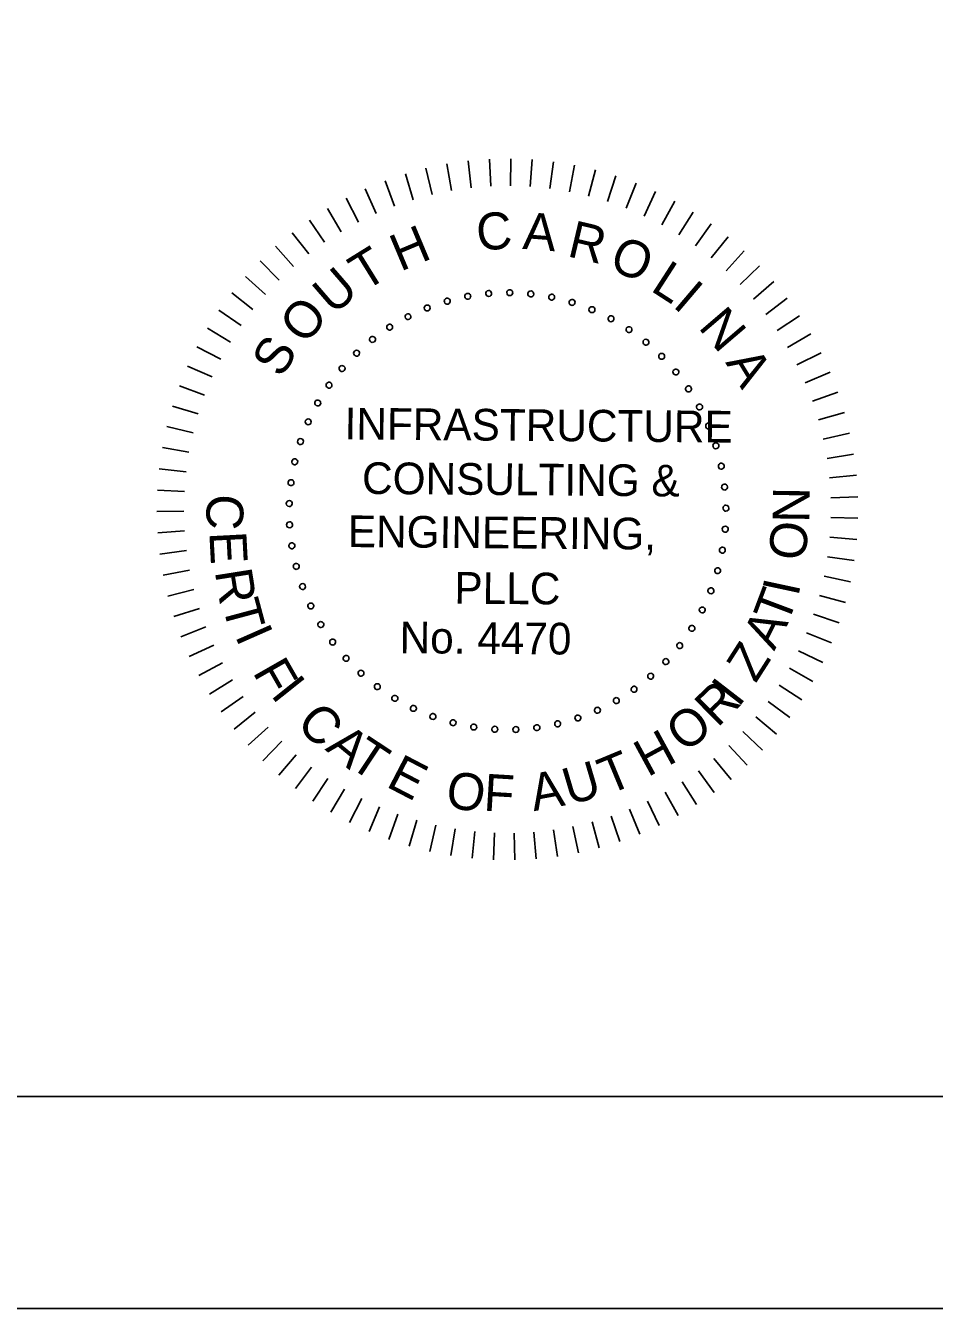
# Model space of a CAD drawing. Extents: x -125.5 to -89.4, y -5.1 to 16.9.
# Drawn here: x -100.338 to -98.192, y -5.066 to -2.039 of the extents above; entities that cross this region are included whole.
import ezdxf

# ---------------------------------------------------------------- set-up
doc = ezdxf.new("R2010")
doc.units = 0
for name, color, linetype in [('BR_BORDER LINES', 7, 'Continuous'), ('BR_TEXT', 7, 'Continuous'), ('Level 31', 7, 'Continuous')]:
    doc.layers.add(name, color=color, linetype=linetype)

msp = doc.modelspace()

# ---------------------------------------------------------------- linework, layer by layer
at = {"layer": 'BR_BORDER LINES'}
msp.add_line((-123.6994, -4.5662), (-90.0334, -4.5662), dxfattribs=at)
at = {"layer": 'BR_TEXT'}
for p, q in [((-99.2931, -2.3579), (-99.2858, -2.4212)), ((-99.2427, -2.3538), (-99.2394, -2.4174)), ((-99.1923, -2.3527), (-99.1928, -2.4164)), ((-99.1418, -2.3548), (-99.1462, -2.4183)), ((-99.0916, -2.3599), (-99.0999, -2.423)), ((-99.4412, -2.3886), (-99.4226, -2.4495)), ((-99.3925, -2.3754), (-99.3776, -2.4373)), ((-99.343, -2.3651), (-99.332, -2.4278)), ((-99.0418, -2.368), (-99.0539, -2.4305)), ((-98.9925, -2.3792), (-99.0084, -2.4408)), ((-99.489, -2.4048), (-99.4667, -2.4644)), ((-98.9441, -2.3933), (-98.9637, -2.4539)), ((-98.8966, -2.4104), (-98.9199, -2.4696)), ((-99.5813, -2.4457), (-99.5519, -2.5022)), ((-99.5358, -2.4238), (-99.5099, -2.482)), ((-98.8502, -2.4303), (-98.877, -2.488)), ((-99.6253, -2.4703), (-99.5926, -2.5249)), ((-98.8051, -2.453), (-98.8354, -2.509)), ((-98.7615, -2.4785), (-98.7952, -2.5325)), ((-99.6678, -2.4975), (-99.6318, -2.55)), ((-98.7195, -2.5065), (-98.7564, -2.5584)), ((-99.7086, -2.5273), (-99.6694, -2.5775)), ((-98.6793, -2.5371), (-98.7193, -2.5866)), ((-99.7475, -2.5595), (-99.7053, -2.6072)), ((-98.6411, -2.57), (-98.684, -2.617)), ((-99.7843, -2.5941), (-99.7393, -2.6391)), ((-99.819, -2.6308), (-99.7713, -2.673)), ((-98.6049, -2.6052), (-98.6506, -2.6495)), ((-98.571, -2.6426), (-98.6193, -2.684)), ((-99.8513, -2.6695), (-99.8012, -2.7087)), ((-98.5393, -2.6819), (-98.5901, -2.7204)), ((-99.8813, -2.7102), (-99.8288, -2.7463)), ((-98.5102, -2.7232), (-98.5632, -2.7584)), ((-99.9087, -2.7526), (-99.8541, -2.7854)), ((-98.4836, -2.7661), (-98.5387, -2.798)), ((-99.9334, -2.7965), (-99.877, -2.826)), ((-98.4597, -2.8105), (-98.5166, -2.839)), ((-99.9555, -2.842), (-99.8973, -2.8679)), ((-98.4385, -2.8563), (-98.497, -2.8813)), ((-99.9747, -2.8886), (-99.9151, -2.911)), ((-98.4202, -2.9034), (-98.4801, -2.9248)), ((-99.991, -2.9364), (-99.9302, -2.9551)), ((-98.4047, -2.9514), (-98.4659, -2.9691)), ((-100.0044, -2.9851), (-99.9426, -3)), ((-98.3922, -3.0004), (-98.4544, -3.0143)), ((-100.0149, -3.0345), (-99.9522, -3.0456)), ((-98.3828, -3.05), (-98.4456, -3.0601)), ((-100.0222, -3.0844), (-99.959, -3.0917)), ((-98.3763, -3.1), (-98.4397, -3.1063)), ((-100.0266, -3.1347), (-99.963, -3.1382)), ((-98.373, -3.1504), (-98.4366, -3.1528)), ((-100.0278, -3.1852), (-99.9641, -3.1847)), ((-98.3727, -3.2009), (-98.4363, -3.1994)), ((-100.026, -3.2356), (-99.9625, -3.2313)), ((-98.3755, -3.2513), (-98.4389, -3.2459)), ((-100.0211, -3.2859), (-99.9579, -3.2777)), ((-98.3813, -3.3014), (-98.4443, -3.2922)), ((-100.0131, -3.3357), (-99.9506, -3.3237)), ((-98.3902, -3.3511), (-98.4525, -3.3381)), ((-100.0021, -3.385), (-99.9405, -3.3692)), ((-98.4021, -3.4002), (-98.4635, -3.3834)), ((-99.9882, -3.4335), (-99.9276, -3.414)), ((-98.417, -3.4484), (-98.4773, -3.4279)), ((-99.9713, -3.4811), (-99.912, -3.4579)), ((-98.4348, -3.4957), (-98.4937, -3.4715)), ((-99.9515, -3.5276), (-99.8937, -3.5008)), ((-98.4554, -3.5417), (-98.5128, -3.514)), ((-99.929, -3.5727), (-99.8729, -3.5425)), ((-98.4789, -3.5865), (-98.5344, -3.5553)), ((-99.9037, -3.6164), (-99.8496, -3.5828)), ((-98.505, -3.6297), (-98.5585, -3.5952)), ((-99.8758, -3.6585), (-99.8239, -3.6217)), ((-99.8454, -3.6988), (-99.7958, -3.6589)), ((-98.5336, -3.6712), (-98.5849, -3.6335)), ((-98.5648, -3.7109), (-98.6137, -3.6702)), ((-99.8126, -3.7372), (-99.7655, -3.6943)), ((-98.5983, -3.7487), (-98.6447, -3.705)), ((-99.7775, -3.7735), (-99.7331, -3.7278)), ((-98.6341, -3.7843), (-98.6777, -3.7379)), ((-99.7403, -3.8076), (-99.6988, -3.7593)), ((-98.672, -3.8177), (-98.7126, -3.7687)), ((-99.701, -3.8393), (-99.6626, -3.7886)), ((-98.7118, -3.8487), (-98.7494, -3.7974)), ((-99.6599, -3.8687), (-99.6246, -3.8157)), ((-99.6171, -3.8954), (-99.5851, -3.8404)), ((-98.7534, -3.8772), (-98.7879, -3.8237)), ((-99.5728, -3.9195), (-99.5442, -3.8626)), ((-98.8416, -3.9264), (-98.8692, -3.8691)), ((-98.7967, -3.9032), (-98.8278, -3.8476)), ((-99.527, -3.9408), (-99.5019, -3.8823)), ((-99.48, -3.9594), (-99.4586, -3.8994)), ((-98.935, -3.9645), (-98.9555, -3.9042)), ((-98.8877, -3.9469), (-98.9118, -3.888)), ((-99.432, -3.975), (-99.4143, -3.9138)), ((-99.3832, -3.9876), (-99.3692, -3.9255)), ((-99.3336, -3.9973), (-99.3234, -3.9344)), ((-99.0324, -3.991), (-99.0454, -3.9286)), ((-98.9833, -3.9792), (-99.0001, -3.9178)), ((-99.2836, -4.0039), (-99.2772, -3.9406)), ((-99.2332, -4.0075), (-99.2307, -3.9438)), ((-99.1827, -4.0079), (-99.1841, -3.9443)), ((-99.1323, -4.0053), (-99.1376, -3.9419)), ((-99.0821, -3.9997), (-99.0913, -3.9367))]:
    msp.add_line(p, q, dxfattribs=at)
for centre, start, end in [((-99.2445, -2.6708), 5.0653, 185.0653), ((-99.1947, -2.6689), 359.5268, 179.5268), ((-99.3424, -2.6889), 16.1422, 196.1422), ((-99.3424, -2.6889), 196.1422, 16.1422), ((-99.2939, -2.6775), 10.6038, 190.6038), ((-99.2939, -2.6775), 190.6038, 10.6038), ((-99.2445, -2.6708), 185.0653, 5.0653), ((-99.1947, -2.6689), 179.5268, 359.5268), ((-99.145, -2.6718), 173.9884, 353.9884), ((-99.145, -2.6718), 353.9884, 173.9884), ((-99.0957, -2.6795), 168.4499, 348.4499), ((-99.0957, -2.6795), 348.4499, 168.4499), ((-99.0475, -2.6919), 162.9114, 342.9114), ((-99.0475, -2.6919), 342.9114, 162.9114), ((-99.435, -2.7255), 27.2191, 207.2191), ((-99.435, -2.7255), 207.2191, 27.2191), ((-99.3896, -2.705), 21.6807, 201.6807), ((-99.3896, -2.705), 201.6807, 21.6807), ((-99.0006, -2.709), 157.373, 337.373), ((-99.0006, -2.709), 337.373, 157.373), ((-98.9557, -2.7304), 331.8345, 151.8345), ((-99.4782, -2.7503), 32.7576, 212.7576), ((-99.4782, -2.7503), 212.7576, 32.7576), ((-98.9557, -2.7304), 151.8345, 331.8345), ((-98.913, -2.7561), 146.2961, 326.2961), ((-98.913, -2.7561), 326.2961, 146.2961), ((-99.5188, -2.7792), 38.2961, 218.2961), ((-99.5188, -2.7792), 218.2961, 38.2961), ((-98.873, -2.7858), 140.7576, 320.7576), ((-98.873, -2.7858), 320.7576, 140.7576), ((-99.5564, -2.8119), 43.8345, 223.8345), ((-99.5564, -2.8119), 223.8345, 43.8345), ((-98.836, -2.8192), 135.2191, 315.2191), ((-98.836, -2.8192), 315.2191, 135.2191), ((-99.5907, -2.848), 49.373, 229.373), ((-99.5907, -2.848), 229.373, 49.373), ((-98.8024, -2.8561), 129.6807, 309.6807), ((-98.8024, -2.8561), 309.6807, 129.6807), ((-99.6214, -2.8873), 54.9114, 234.9114), ((-99.6214, -2.8873), 234.9114, 54.9114), ((-98.7726, -2.896), 124.1422, 304.1422), ((-98.7726, -2.896), 304.1422, 124.1422), ((-99.6481, -2.9293), 60.4499, 240.4499), ((-99.6481, -2.9293), 240.4499, 60.4499), ((-98.7467, -2.9386), 118.6038, 298.6038), ((-98.7467, -2.9386), 298.6038, 118.6038), ((-99.6706, -2.9738), 65.9884, 245.9884), ((-99.6706, -2.9738), 245.9884, 65.9884), ((-98.7251, -2.9835), 113.0653, 293.0653), ((-98.7251, -2.9835), 293.0653, 113.0653), ((-99.6888, -3.0202), 71.5268, 251.5268), ((-99.6888, -3.0202), 251.5268, 71.5268), ((-98.7079, -3.0302), 107.5268, 287.5268), ((-98.7079, -3.0302), 287.5268, 107.5268), ((-99.7024, -3.0681), 77.0653, 257.0653), ((-99.7024, -3.0681), 257.0653, 77.0653), ((-98.6953, -3.0785), 101.9884, 281.9884), ((-98.6953, -3.0785), 281.9884, 101.9884), ((-99.7113, -3.1172), 82.6038, 262.6038), ((-99.7113, -3.1172), 262.6038, 82.6038), ((-98.6874, -3.1277), 96.4499, 276.4499), ((-98.6874, -3.1277), 276.4499, 96.4499), ((-99.7154, -3.1668), 88.1422, 268.1422), ((-99.7154, -3.1668), 268.1422, 88.1422), ((-98.6843, -3.1774), 90.9114, 270.9114), ((-98.6843, -3.1774), 270.9114, 90.9114), ((-99.7147, -3.2167), 93.6807, 273.6807), ((-99.7147, -3.2167), 273.6807, 93.6807), ((-98.686, -3.2272), 85.373, 265.373), ((-98.686, -3.2272), 265.373, 85.373), ((-99.7092, -3.2662), 99.2191, 279.2191), ((-99.7092, -3.2662), 279.2191, 99.2191), ((-98.6926, -3.2766), 79.8345, 259.8345), ((-98.6926, -3.2766), 259.8345, 79.8345), ((-99.6989, -3.3149), 104.7576, 284.7576), ((-99.6989, -3.3149), 284.7576, 104.7576), ((-98.7038, -3.3251), 74.2961, 254.2961), ((-98.7038, -3.3251), 254.2961, 74.2961), ((-99.684, -3.3625), 110.2961, 290.2961), ((-99.684, -3.3625), 290.2961, 110.2961), ((-98.7197, -3.3724), 68.7576, 248.7576), ((-98.7197, -3.3724), 248.7576, 68.7576), ((-99.6646, -3.4084), 115.8345, 295.8345), ((-99.6646, -3.4084), 295.8345, 115.8345), ((-98.7401, -3.4178), 63.2191, 243.2191), ((-98.7401, -3.4178), 243.2191, 63.2191), ((-99.6408, -3.4522), 121.373, 301.373), ((-99.6408, -3.4522), 301.373, 121.373), ((-98.7647, -3.4611), 57.6807, 237.6807), ((-98.7647, -3.4611), 237.6807, 57.6807), ((-99.6129, -3.4935), 126.9114, 306.9114), ((-99.6129, -3.4935), 306.9114, 126.9114), ((-98.7934, -3.5019), 52.1422, 232.1422), ((-98.7934, -3.5019), 232.1422, 52.1422), ((-99.5812, -3.5319), 132.4499, 312.4499), ((-99.5812, -3.5319), 312.4499, 132.4499), ((-98.826, -3.5396), 46.6038, 226.6038), ((-98.826, -3.5396), 226.6038, 46.6038), ((-99.5459, -3.5671), 137.9884, 317.9884), ((-99.5459, -3.5671), 317.9884, 137.9884), ((-98.862, -3.5741), 41.0653, 221.0653), ((-98.862, -3.5741), 221.0653, 41.0653), ((-99.5074, -3.5987), 143.5268, 323.5268), ((-99.5074, -3.5987), 323.5268, 143.5268), ((-98.9012, -3.6049), 35.5268, 215.5268), ((-98.9012, -3.6049), 215.5268, 35.5268), ((-99.466, -3.6264), 149.0653, 329.0653), ((-99.466, -3.6264), 329.0653, 149.0653), ((-98.9431, -3.6317), 29.9884, 209.9884), ((-98.9431, -3.6317), 209.9884, 29.9884), ((-99.4221, -3.65), 154.6038, 334.6038), ((-99.4221, -3.65), 334.6038, 154.6038), ((-99.3761, -3.6693), 340.1422, 160.1422), ((-98.9875, -3.6545), 24.4499, 204.4499), ((-98.9875, -3.6545), 204.4499, 24.4499), ((-99.3761, -3.6693), 160.1422, 340.1422), ((-99.3285, -3.684), 165.6807, 345.6807), ((-99.3285, -3.684), 345.6807, 165.6807), ((-99.2797, -3.6941), 351.2191, 171.2191), ((-99.2797, -3.6941), 171.2191, 351.2191), ((-99.2302, -3.6994), 356.7576, 176.7576), ((-99.1803, -3.6999), 2.2961, 182.2961), ((-99.1307, -3.6956), 7.8345, 187.8345), ((-99.0817, -3.6865), 13.373, 193.373), ((-99.0817, -3.6865), 193.373, 13.373), ((-99.0338, -3.6728), 18.9114, 198.9114), ((-99.0338, -3.6728), 198.9114, 18.9114), ((-99.2302, -3.6994), 176.7576, 356.7576), ((-99.1803, -3.6999), 182.2961, 2.2961), ((-99.1307, -3.6956), 187.8345, 7.8345)]:
    msp.add_arc(centre, 0.00701, start, end, dxfattribs=at)
at = {"layer": 'Level 31'}
msp.add_lwpolyline([(-125.5328, -5.0661), (-89.5328, -5.0661), (-89.5328, 16.9339), (-125.5328, 16.9339)], close=True, dxfattribs=at)

# ---------------------------------------------------------------- texts
at = {"layer": 'BR_TEXT'}
for s, height, rotation, p in [('C', 0.0872, 4.7281, (-99.2702, -2.5703)), ('A', 0.0872, 355.6981, (-99.1657, -2.5654)), ('H', 0.0872, 22.7882, (-99.453, -2.6197)), ('R', 0.0872, 346.6681, (-99.0615, -2.5824)), ('O', 0.0872, 337.638, (-98.9637, -2.6122)), ('T', 0.0872, 31.8182, (-99.5379, -2.6674)), ('L', 0.0872, 327.108, (-98.8649, -2.6626)), ('U', 0.0872, 40.8482, (-99.6112, -2.7235)), ('I', 0.0872, 319.578, (-98.8123, -2.7005)), ('O', 0.0872, 49.8782, (-99.6782, -2.7945)), ('N', 0.0872, 310.548, (-98.7515, -2.7512)), ('S', 0.0872, 58.9083, (-99.7336, -2.8727)), ('A', 0.0872, 301.5179, (-98.6864, -2.8336)), ('INFRASTRUCTURE', 0.074771, 359.5268, (-99.585, -3.0152)), ('CONSULTING &', 0.074771, 359.5268, (-99.5437, -3.1438)), ('N', 0.0872, 89.2085, (-98.4872, -3.2124)), ('C', 0.0872, 267.025, (-99.9086, -3.1426)), ('ENGINEERING,', 0.074771, 359.5268, (-99.5773, -3.2693)), ('E', 0.0872, 273.025, (-99.9042, -3.2342)), ('O', 0.0872, 83.2085, (-98.4982, -3.3038)), ('R', 0.0872, 279.025, (-99.8914, -3.3265)), ('PLLC', 0.07477, 359.5268, (-99.3256, -3.4028)), ('I', 0.0872, 77.9093, (-98.5137, -3.3881)), ('T', 0.0872, 285.025, (-99.874, -3.4053)), ('T', 0.0872, 69.3954, (-98.5394, -3.4556)), ('No. 4470', 0.07477, 359.5268, (-99.4551, -3.5197)), ('A', 0.0872, 63.3954, (-98.5702, -3.516)), ('I', 0.0872, 293.7713, (-99.8443, -3.4784)), ('Z', 0.0872, 57.3954, (-98.6141, -3.5923)), ('F', 0.0872, 299.7713, (-99.8031, -3.5644)), ('I', 0.0872, 308.5268, (-99.761, -3.6183)), ('R', 0.0872, 44.5268, (-98.7045, -3.6973)), ('I', 0.0872, 52.3339, (-98.6551, -3.65)), ('C', 0.0872, 314.5268, (-99.7017, -3.6884)), ('O', 0.0872, 38.5268, (-98.7811, -3.7572)), ('A', 0.0872, 320.5268, (-99.6325, -3.747)), ('T', 0.0872, 326.5268, (-99.5781, -3.7855)), ('H', 0.0872, 28.5268, (-98.8692, -3.8132)), ('T', 0.0872, 22.5268, (-98.9624, -3.855)), ('E', 0.0872, 332.5268, (-99.4895, -3.8332)), ('U', 0.0872, 16.5268, (-99.0541, -3.8794)), ('O', 0.0872, 350.5268, (-99.3494, -3.8821)), ('F', 0.0872, 356.5268, (-99.2579, -3.8912)), ('A', 0.0872, 10.5268, (-99.138, -3.8929))]:
    msp.add_text(s, height=height, rotation=rotation, dxfattribs=at).set_placement(p)

doc.saveas('drawing.dxf')
